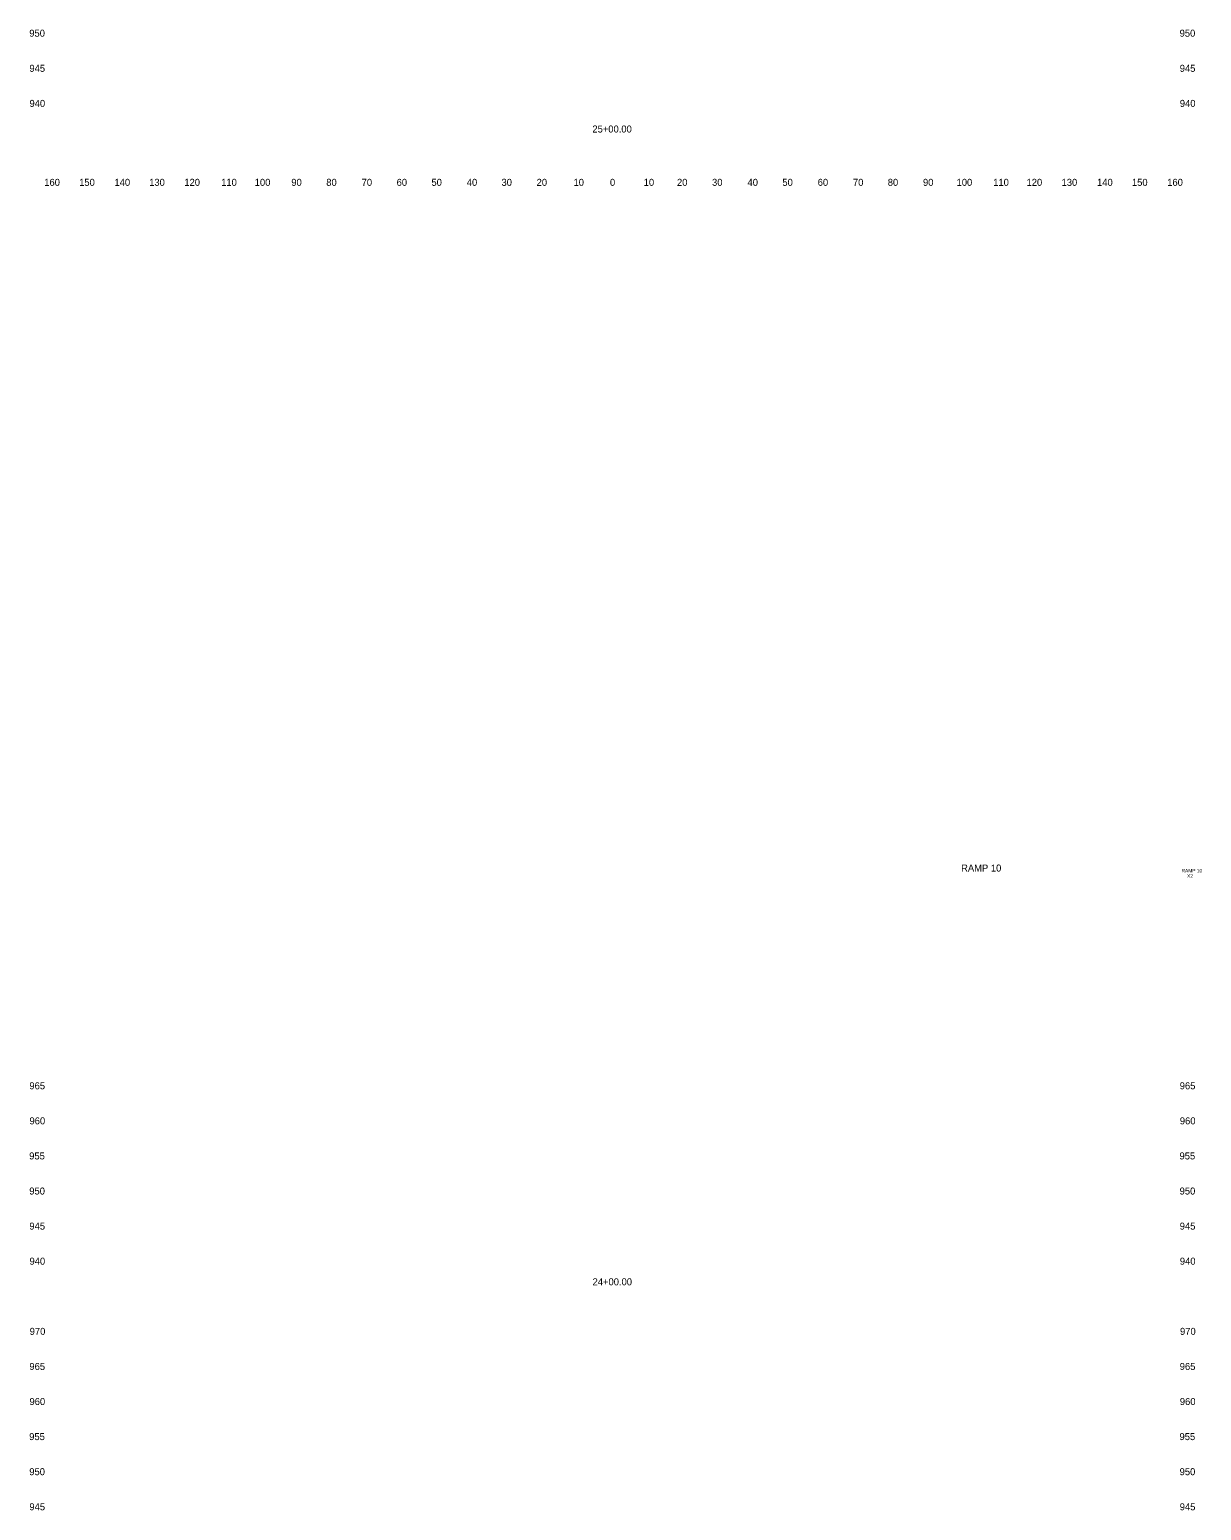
# Model space of a CAD drawing. Extents: x 4994 to 5328, y 4997 to 8404.
# Drawn here: x 4993.9 to 5327.8, y 5420 to 5842 of the extents above; entities that cross this region are included whole.
import ezdxf

# ---------------------------------------------------------------- set-up
doc = ezdxf.new("R2010")
doc.units = 0
for name, color, linetype in [('RD_SHT_ID', 7, 'Continuous'), ('RD_XS_TX_Offset', 7, 'Continuous'), ('RD_XS_TX_Station', 7, 'Continuous')]:
    doc.layers.add(name, color=color, linetype=linetype)

msp = doc.modelspace()

# ---------------------------------------------------------------- texts
at = {"layer": 'RD_SHT_ID'}
for s, height, p in [('RAMP 10', 2, (5259.37, 5602.06)), ('RAMP 10', 1, (5322.16, 5601.8)), ('X2', 1, (5323.74, 5600.3))]:
    msp.add_text(s, height=height, dxfattribs=at).set_placement(p)
at = {"layer": 'RD_XS_TX_Offset'}
for s, p in [('950', (4993.83, 5840)), ('950', (5321.63, 5840)), ('945', (4993.86, 5830)), ('945', (5321.66, 5830)), ('940', (4993.89, 5820)), ('940', (5321.69, 5820)), ('160', (4998.1, 5797.5)), ('150', (5008.04, 5797.5)), ('140', (5018.1, 5797.5)), ('130', (5027.99, 5797.5)), ('120', (5038.01, 5797.5)), ('110', (5048.51, 5797.5)), ('100', (5058.07, 5797.5)), ('90', (5068.5, 5797.5)), ('80', (5078.46, 5797.5)), ('70', (5088.54, 5797.5)), ('60', (5098.5, 5797.5)), ('50', (5108.43, 5797.5)), ('40', (5118.5, 5797.5)), ('30', (5128.39, 5797.5)), ('20', (5138.4, 5797.5)), ('10', (5148.91, 5797.5)), ('0', (5159.3, 5797.5)), ('0', (5159.3, 5797.5)), ('10', (5168.91, 5797.5)), ('20', (5178.4, 5797.5)), ('30', (5188.39, 5797.5)), ('40', (5198.5, 5797.5)), ('50', (5208.43, 5797.5)), ('60', (5218.5, 5797.5)), ('70', (5228.54, 5797.5)), ('80', (5238.46, 5797.5)), ('90', (5248.5, 5797.5)), ('100', (5258.07, 5797.5)), ('110', (5268.51, 5797.5)), ('120', (5278.01, 5797.5)), ('130', (5287.99, 5797.5)), ('140', (5298.1, 5797.5)), ('150', (5308.04, 5797.5)), ('160', (5318.1, 5797.5)), ('965', (4993.86, 5540)), ('965', (5321.66, 5540)), ('960', (4993.89, 5530)), ('960', (5321.69, 5530)), ('955', (4993.8, 5520)), ('955', (5321.6, 5520)), ('950', (4993.83, 5510)), ('950', (5321.63, 5510)), ('945', (4993.86, 5500)), ('945', (5321.66, 5500)), ('940', (4993.89, 5490)), ('940', (5321.69, 5490)), ('970', (4993.94, 5470)), ('970', (5321.74, 5470)), ('965', (4993.86, 5460)), ('965', (5321.66, 5460)), ('960', (4993.89, 5450)), ('960', (5321.69, 5450)), ('955', (4993.8, 5440)), ('955', (5321.6, 5440)), ('950', (4993.83, 5430)), ('950', (5321.63, 5430)), ('945', (4993.86, 5420)), ('945', (5321.66, 5420))]:
    msp.add_text(s, height=2, dxfattribs=at).set_placement(p)
at = {"layer": 'RD_XS_TX_Station'}
for s, p in [('25+00.00', (5154.29, 5812.7)), ('24+00.00', (5154.35, 5484.13))]:
    msp.add_text(s, height=2, dxfattribs=at).set_placement(p)

doc.saveas('drawing.dxf')
